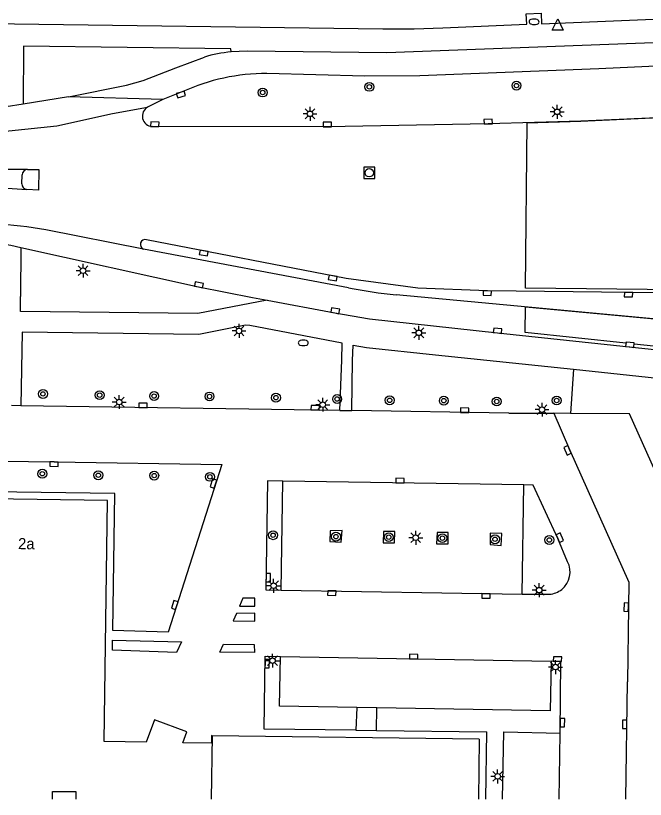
# Model space of a CAD drawing. Extents: x 132573 to 132944, y 398226 to 398676.
# Drawn here: x 132651.3 to 132708, y 398226.3 to 398296.9 of the extents above; entities that cross this region are included whole.
import ezdxf

# ---------------------------------------------------------------- set-up
doc = ezdxf.new("R2010")
doc.units = 0
for name, color, linetype in [('gg-anno-huisnummerreeks BGT', 7, 'Continuous'), ('gg-bbg-bijgebouw', 7, 'Continuous'), ('gg-bbg-hoofdgebouw', 7, 'Continuous'), ('gg-bbg-tussenscheiding', 7, 'Continuous'), ('gg-knt-verharding', 7, 'Continuous'), ('gg-knt-verharding nz', 7, 'Continuous'), ('gt-grn-groengrens', 7, 'Continuous'), ('gt-symb-boom', 7, 'Continuous'), ('gt-symb-brandkraan', 7, 'Continuous'), ('gt-symb-kolk', 7, 'Continuous'), ('gt-symb-lichtmast', 7, 'Continuous'), ('gt-symb-rioolschacht', 7, 'Continuous'), ('gt-symb-waterafsluiter', 7, 'Continuous'), ('ir-asfa-asfalt arcering', 7, 'Continuous'), ('ir-asfa-asfalt rood', 7, 'Continuous')]:
    doc.layers.add(name, color=color, linetype=linetype)

msp = doc.modelspace()

# ---------------------------------------------------------------- linework, layer by layer
at = {"layer": 'gg-bbg-bijgebouw'}
for q in [(132669.037, 398232.033), (132693.005, 398226.299)]:
    msp.add_line((132693.081, 398231.724), q, dxfattribs=at)
at = {"layer": 'gg-bbg-hoofdgebouw'}
msp.add_line((132654.642, 398226.299), (132654.65, 398227.008), dxfattribs=at)
for points in [[(132669.037, 398232.033), (132668.968, 398232.034), (132668.959, 398231.354), (132666.379, 398231.379), (132666.738, 398232.375), (132663.817, 398233.469), (132663.084, 398231.446), (132659.296, 398231.499), (132659.594, 398253.222), (132644.751, 398253.437)], [(132654.65, 398227.008), (132656.748, 398226.99), (132656.743, 398226.299)]]:
    msp.add_lwpolyline(points, dxfattribs=at)
at = {"layer": 'gg-bbg-tussenscheiding'}
msp.add_line((132669.037, 398232.033), (132668.946, 398226.299), dxfattribs=at)
at = {"layer": 'gg-knt-verharding'}
for p, q in [((132652.023, 398294.151), (132651.99, 398288.915)), ((132665.755, 398292.203), (132668.318, 398293.165)), ((132666.369, 398290.048), (132664.567, 398289.34)), ((132656.09, 398289.574), (132651.99, 398288.915)), ((132664.567, 398289.34), (132656.09, 398289.574)), ((132664.567, 398289.34), (132663.212, 398288.654)), ((132652.393, 398283.027), (132649.013, 398283.031)), ((132651.891, 398281.742), (132651.895, 398282.544)), ((132648.993, 398281.456), (132652.319, 398281.231)), ((132651.786, 398276.006), (132651.766, 398271.608)), ((132681.291, 398272.381), (132662.846, 398275.871)), ((132724.373, 398268.129), (132685.592, 398271.736)), ((132672.662, 398271.512), (132673.971, 398271.264)), ((132651.906, 398268.372), (132651.797, 398261.747)), ((132651.797, 398261.747), (132650.951, 398261.76)), ((132680.53, 398261.337), (132651.797, 398261.747)), ((132680.53, 398261.337), (132681.612, 398261.338)), ((132695.746, 398261.077), (132681.612, 398261.338)), ((132695.746, 398261.077), (132699.791, 398261.072)), ((132701.319, 398261.059), (132699.791, 398261.072)), ((132674.011, 398254.983), (132673.865, 398245.174)), ((132675.393, 398254.962), (132674.011, 398254.983)), ((132675.241, 398245.145), (132675.393, 398254.962)), ((132696.954, 398244.777), (132697.089, 398254.629)), ((132697.93, 398254.611), (132697.089, 398254.629)), ((132673.865, 398245.174), (132675.241, 398245.145)), ((132696.954, 398244.777), (132699.42, 398244.766)), ((132673.808, 398239.18), (132675.174, 398239.171)), ((132699.559, 398238.736), (132699.486, 398234.262)), ((132700.439, 398238.726), (132699.559, 398238.736)), ((132700.369, 398232.25), (132700.439, 398238.726)), ((132682.043, 398234.568), (132681.957, 398232.528)), ((132683.872, 398234.536), (132682.043, 398234.568)), ((132683.826, 398232.506), (132683.872, 398234.536)), ((132699.486, 398234.262), (132683.872, 398234.536)), ((132681.957, 398232.528), (132683.826, 398232.506)), ((132683.826, 398232.506), (132693.755, 398232.39)), ((132693.68, 398226.299), (132693.755, 398232.39))]:
    msp.add_line(p, q, dxfattribs=at)
for points in [[(132641.795, 398296.302), (132648.956, 398296.181), (132684.391, 398295.715), (132687.235, 398295.695), (132689.791, 398295.782), (132697.371, 398296.112), (132697.318, 398297.051), (132698.666, 398297.112), (132698.695, 398296.159), (132713.84, 398296.787), (132716.243, 398298.031), (132718.865, 398298.287), (132721.089, 398298.822)], [(132715.972, 398294.725), (132684.747, 398293.547), (132672.177, 398293.687), (132671.452, 398293.676), (132670.729, 398293.626)], [(132670.729, 398293.626), (132670.696, 398293.918), (132652.023, 398294.151)], [(132656.09, 398289.574), (132661.316, 398290.625), (132662.811, 398291.045), (132665.755, 398292.203)], [(132716.072, 398292.658), (132703.845, 398292.111), (132687.719, 398291.469), (132682.765, 398291.453), (132673.952, 398291.69)], [(132651.99, 398288.915), (132650.473, 398288.671), (132649.708, 398288.596)], [(132724.539, 398288.616), (132710.496, 398287.759), (132702.248, 398287.375), (132693.89, 398287.149), (132679.391, 398286.885), (132663.62, 398286.911)], [(132652.393, 398283.027), (132653.403, 398283.028), (132653.387, 398281.182), (132652.319, 398281.231)], [(132724.668, 398271.755), (132693.813, 398272.093), (132687.563, 398272.351), (132681.105, 398273.227), (132663.109, 398276.707)], [(132649.536, 398276.343), (132650.385, 398276.294), (132650.888, 398276.205), (132651.786, 398276.006)], [(132651.786, 398276.006), (132667.79, 398272.455), (132672.662, 398271.512)], [(132673.971, 398271.264), (132667.718, 398270.065), (132651.76, 398270.254), (132651.766, 398271.608)], [(132673.971, 398271.264), (132680.079, 398270.108), (132683.188, 398269.568), (132694.714, 398268.311), (132723.823, 398265.242)], [(132680.53, 398261.337), (132680.715, 398265.855), (132680.74, 398267.401), (132672.416, 398268.975), (132672.033, 398269.023), (132667.829, 398268.177), (132651.906, 398268.372)], [(132681.612, 398261.338), (132681.675, 398265.839), (132681.722, 398267.224), (132682.936, 398267.007), (132689.144, 398266.333), (132701.574, 398265.046)], [(132701.574, 398265.046), (132715.024, 398263.598), (132719.046, 398263.257)], [(132711.191, 398250.839), (132706.624, 398261.016), (132701.319, 398261.059)], [(132626.867, 398257.057), (132654.785, 398256.69), (132669.886, 398256.449)], [(132669.886, 398256.449), (132665.058, 398241.351), (132660.06, 398241.502), (132660.243, 398253.839), (132644.759, 398254.063)], [(132701.043, 398247.707), (132700.16, 398249.784), (132697.93, 398254.611)], [(132680.648, 398249.47), (132680.734, 398250.501), (132679.663, 398250.485), (132679.633, 398249.516), (132680.648, 398249.47)], [(132685.435, 398249.405), (132685.475, 398250.411), (132684.446, 398250.436), (132684.424, 398249.402), (132685.435, 398249.405)], [(132690.285, 398249.304), (132690.298, 398250.341), (132689.282, 398250.321), (132689.236, 398249.311), (132690.285, 398249.304)], [(132695.127, 398250.252), (132694.076, 398250.269), (132694.053, 398249.253), (132695.055, 398249.169), (132695.127, 398250.252)], [(132672.866, 398243.684), (132672.881, 398244.411), (132671.794, 398244.417), (132671.479, 398243.7), (132672.866, 398243.684)], [(132672.852, 398242.344), (132672.859, 398243.056), (132671.221, 398243.042), (132670.926, 398242.368), (132672.852, 398242.344)], [(132666.274, 398240.482), (132665.81, 398239.513), (132660.055, 398239.747), (132660.054, 398240.641), (132666.274, 398240.482)], [(132669.725, 398239.567), (132670.039, 398240.265), (132672.819, 398240.242), (132672.827, 398239.518), (132669.725, 398239.567)], [(132681.957, 398232.528), (132673.703, 398232.624), (132673.808, 398239.18)], [(132682.043, 398234.568), (132675.103, 398234.69), (132675.174, 398239.171)], [(132695.178, 398226.299), (132695.306, 398232.364), (132700.369, 398232.25)]]:
    msp.add_lwpolyline(points, dxfattribs=at)
for centre, radius, start, end in [((132672.022, 398280.326), 13.363, 95.5547, 106.09469), ((132673.958, 398273.331), 18.359, 90.01888, 114.41718), ((132663.664, 398287.84), 0.931, 119.03995, 267.30913), ((132652.395, 398282.527), 0.5, 90.25109, 177.99688), ((132652.378, 398281.715), 0.488, 176.82866, 263.06863), ((132662.991, 398276.285), 0.438, 74.34625, 250.72729), ((132690.707, 398320.509), 49.041, 258.92976, 264.01262), ((132699.232, 398246.788), 2.031, 308.96553, 26.90135), ((132699.231, 398246.791), 2.034, 275.3344, 308.93812)]:
    msp.add_arc(centre, radius, start, end, dxfattribs=at)
at = {"layer": 'gg-knt-verharding nz'}
for p, q in [((132662.846, 398275.871), (132654.053, 398277.599)), ((132697.089, 398254.629), (132675.393, 398254.962)), ((132675.241, 398245.145), (132696.954, 398244.777)), ((132675.174, 398239.171), (132699.559, 398238.736)), ((132706.292, 398226.299), (132706.437, 398236.895)), ((132700.287, 398226.299), (132700.369, 398232.25))]:
    msp.add_line(p, q, dxfattribs=at)
for points in [[(132595.104, 398287.061), (132636.866, 398286.381), (132649.245, 398286.381), (132655.041, 398286.969), (132660.032, 398288.081), (132663.212, 398288.654)], [(132699.791, 398261.072), (132701.213, 398257.819), (132706.561, 398245.852), (132706.518, 398243.601), (132706.437, 398236.895)]]:
    msp.add_lwpolyline(points, dxfattribs=at)
msp.add_arc((132647.794, 398243.162), 35.001, 79.69889, 87.3244, dxfattribs=at)
at = {"layer": 'gt-grn-groengrens'}
msp.add_line((132701.574, 398265.046), (132701.319, 398261.059), dxfattribs=at)
at = {"layer": 'gt-symb-boom'}
for centre, radius in [((132683.182, 398290.477), 0.4), ((132683.182, 398290.477), 0.2), ((132696.435, 398290.592), 0.4), ((132696.435, 398290.592), 0.2), ((132673.57, 398289.966), 0.4), ((132673.57, 398289.966), 0.2), ((132653.779, 398262.816), 0.4), ((132653.779, 398262.816), 0.2), ((132658.892, 398262.706), 0.4), ((132658.892, 398262.706), 0.2), ((132663.793, 398262.623), 0.4), ((132663.793, 398262.623), 0.2), ((132668.788, 398262.589), 0.4), ((132668.788, 398262.589), 0.2), ((132674.766, 398262.479), 0.4), ((132674.766, 398262.479), 0.2), ((132680.28, 398262.358), 0.4), ((132680.28, 398262.358), 0.2), ((132685.016, 398262.243), 0.4), ((132685.016, 398262.243), 0.2), ((132689.89, 398262.208), 0.4), ((132694.661, 398262.134), 0.4), ((132700.057, 398262.225), 0.4), ((132700.057, 398262.225), 0.2), ((132689.89, 398262.208), 0.2), ((132694.661, 398262.134), 0.2), ((132653.722, 398255.627), 0.4), ((132653.722, 398255.627), 0.2), ((132658.769, 398255.491), 0.4), ((132658.769, 398255.491), 0.2), ((132663.804, 398255.462), 0.4), ((132663.804, 398255.462), 0.2), ((132668.823, 398255.345), 0.4), ((132668.823, 398255.345), 0.2), ((132674.511, 398250.088), 0.4), ((132674.511, 398250.088), 0.2), ((132680.171, 398249.962), 0.4), ((132680.171, 398249.962), 0.2), ((132684.932, 398249.916), 0.4), ((132684.932, 398249.916), 0.2), ((132689.766, 398249.823), 0.4), ((132689.766, 398249.823), 0.2), ((132694.499, 398249.726), 0.4), ((132694.499, 398249.726), 0.2), ((132699.394, 398249.66), 0.4), ((132699.394, 398249.66), 0.2)]:
    msp.add_circle(centre, radius, dxfattribs=at)
at = {"layer": 'gt-symb-brandkraan'}
for centre, radius, start, end in [((132697.774, 398296.351), 0.206, 104.74122, 249.60736), ((132698.485, 398293.649), 3, 104.06633, 104.74122), ((132697.984, 398295.649), 0.938, 70.28224, 104.06633), ((132697.288, 398293.708), 3, 69.60734, 70.28224), ((132698.262, 398296.327), 0.206, 284.74121, 69.60734), ((132698.748, 398298.97), 3, 249.60736, 250.28226), ((132698.052, 398297.029), 0.938, 250.28226, 284.06631), ((132697.551, 398299.029), 3, 284.06631, 284.74121), ((132676.991, 398267.414), 0.206, 107.56694, 252.43307), ((132677.834, 398264.75), 3, 106.89205, 107.56694), ((132677.235, 398266.723), 0.938, 73.10799, 106.89205), ((132676.636, 398264.75), 3, 72.43309, 73.10799), ((132677.479, 398267.414), 0.206, 287.56695, 72.43309), ((132677.834, 398270.078), 3, 252.43307, 253.10797), ((132677.235, 398268.105), 0.938, 253.10797, 286.89206), ((132676.636, 398270.078), 3, 286.89206, 287.56695)]:
    msp.add_arc(centre, radius, start, end, dxfattribs=at)
at = {"layer": 'gt-symb-kolk'}
for points in [[(132666.151, 398289.979), (132665.794, 398289.865), (132665.915, 398289.484), (132666.63, 398289.712), (132666.508, 398290.093), (132666.151, 398289.979)], [(132663.854, 398286.908), (132664.229, 398286.903), (132664.235, 398287.303), (132663.485, 398287.313), (132663.479, 398286.913), (132663.854, 398286.908)], [(132679.391, 398286.885), (132679.766, 398286.885), (132679.766, 398287.285), (132679.016, 398287.285), (132679.016, 398286.885), (132679.391, 398286.885)], [(132693.89, 398287.149), (132694.265, 398287.156), (132694.258, 398287.556), (132693.508, 398287.542), (132693.515, 398287.142), (132693.89, 398287.149)], [(132668.301, 398275.707), (132667.933, 398275.778), (132667.857, 398275.385), (132668.594, 398275.243), (132668.669, 398275.636), (132668.301, 398275.707)], [(132679.927, 398273.457), (132679.559, 398273.528), (132679.483, 398273.136), (132680.219, 398272.993), (132680.295, 398273.386), (132679.927, 398273.457)], [(132667.79, 398272.455), (132668.158, 398272.384), (132668.234, 398272.776), (132667.498, 398272.919), (132667.422, 398272.526), (132667.79, 398272.455)], [(132693.813, 398272.093), (132693.438, 398272.108), (132693.422, 398271.709), (132694.171, 398271.678), (132694.188, 398272.078), (132693.813, 398272.093)], [(132706.531, 398271.954), (132706.156, 398271.958), (132706.152, 398271.558), (132706.902, 398271.55), (132706.906, 398271.95), (132706.531, 398271.954)], [(132680.079, 398270.108), (132680.448, 398270.044), (132680.517, 398270.438), (132679.778, 398270.566), (132679.71, 398270.172), (132680.079, 398270.108)], [(132694.714, 398268.311), (132695.087, 398268.271), (132695.129, 398268.669), (132694.383, 398268.748), (132694.341, 398268.351), (132694.714, 398268.311)], [(132706.637, 398267.046), (132707.01, 398267.007), (132707.052, 398267.405), (132706.306, 398267.483), (132706.264, 398267.085), (132706.637, 398267.046)], [(132662.79, 398261.58), (132663.165, 398261.574), (132663.171, 398261.974), (132662.421, 398261.986), (132662.415, 398261.586), (132662.79, 398261.58)], [(132678.298, 398261.372), (132678.673, 398261.367), (132678.678, 398261.767), (132677.928, 398261.777), (132677.923, 398261.377), (132678.298, 398261.372)], [(132691.777, 398261.149), (132692.152, 398261.143), (132692.159, 398261.543), (132691.409, 398261.555), (132691.402, 398261.155), (132691.777, 398261.149)], [(132701.213, 398257.819), (132701.063, 398258.163), (132700.696, 398258.002), (132700.997, 398257.315), (132701.363, 398257.475), (132701.213, 398257.819)], [(132654.785, 398256.69), (132654.41, 398256.695), (132654.404, 398256.295), (132655.154, 398256.285), (132655.16, 398256.685), (132654.785, 398256.69)], [(132669.331, 398254.698), (132669.444, 398255.055), (132669.063, 398255.176), (132668.836, 398254.461), (132669.218, 398254.341), (132669.331, 398254.698)], [(132685.931, 398254.814), (132686.306, 398254.808), (132686.313, 398255.208), (132685.563, 398255.22), (132685.556, 398254.82), (132685.931, 398254.814)], [(132700.16, 398249.784), (132700.317, 398249.444), (132700.68, 398249.611), (132700.366, 398250.292), (132700.003, 398250.124), (132700.16, 398249.784)], [(132673.877, 398246.272), (132673.871, 398245.897), (132674.271, 398245.891), (132674.283, 398246.641), (132673.883, 398246.647), (132673.877, 398246.272)], [(132679.807, 398245.076), (132679.432, 398245.082), (132679.426, 398244.682), (132680.176, 398244.67), (132680.182, 398245.07), (132679.807, 398245.076)], [(132693.696, 398244.823), (132693.321, 398244.83), (132693.314, 398244.43), (132694.064, 398244.416), (132694.071, 398244.816), (132693.696, 398244.823)], [(132665.843, 398243.744), (132665.957, 398244.101), (132665.575, 398244.223), (132665.348, 398243.508), (132665.729, 398243.387), (132665.843, 398243.744)], [(132706.518, 398243.601), (132706.525, 398243.976), (132706.125, 398243.984), (132706.111, 398243.234), (132706.511, 398243.226), (132706.518, 398243.601)], [(132687.182, 398238.958), (132687.557, 398238.951), (132687.564, 398239.351), (132686.814, 398239.365), (132686.807, 398238.965), (132687.182, 398238.958)], [(132700.126, 398238.73), (132700.501, 398238.721), (132700.511, 398239.121), (132699.761, 398239.139), (132699.751, 398238.739), (132700.126, 398238.73)], [(132673.786, 398238.521), (132673.774, 398238.146), (132674.173, 398238.133), (132674.198, 398238.883), (132673.798, 398238.896), (132673.786, 398238.521)], [(132700.379, 398233.209), (132700.374, 398232.834), (132700.774, 398232.829), (132700.784, 398233.579), (132700.384, 398233.584), (132700.379, 398233.209)], [(132706.381, 398233.043), (132706.386, 398233.418), (132705.986, 398233.424), (132705.976, 398232.674), (132706.376, 398232.668), (132706.381, 398233.043)]]:
    msp.add_lwpolyline(points, dxfattribs=at)
at = {"layer": 'gt-symb-lichtmast'}
for p, q in [((132677.838, 398288.295), (132677.838, 398288.67)), ((132699.927, 398288.407), (132699.662, 398288.672)), ((132700.104, 398288.48), (132700.104, 398288.855)), ((132700.281, 398288.407), (132700.546, 398288.672)), ((132677.588, 398288.045), (132677.213, 398288.045)), ((132677.661, 398288.222), (132677.396, 398288.487)), ((132677.661, 398287.868), (132677.396, 398287.603)), ((132678.015, 398288.222), (132678.28, 398288.487)), ((132678.28, 398287.603), (132678.015, 398287.868)), ((132678.088, 398288.045), (132678.463, 398288.045)), ((132699.854, 398288.23), (132699.479, 398288.23)), ((132699.927, 398288.053), (132699.662, 398287.788)), ((132700.104, 398287.98), (132700.104, 398287.605)), ((132700.546, 398287.788), (132700.281, 398288.053)), ((132700.354, 398288.23), (132700.729, 398288.23)), ((132677.838, 398287.795), (132677.838, 398287.42)), ((132657.393, 398274.166), (132657.393, 398274.541)), ((132657.143, 398273.916), (132656.768, 398273.916)), ((132657.216, 398274.093), (132656.951, 398274.358)), ((132657.216, 398273.739), (132656.951, 398273.474)), ((132657.57, 398274.093), (132657.835, 398274.358)), ((132657.835, 398273.474), (132657.57, 398273.739)), ((132657.643, 398273.916), (132658.018, 398273.916)), ((132657.393, 398273.666), (132657.393, 398273.291)), ((132671.267, 398268.67), (132671.002, 398268.935)), ((132671.444, 398268.743), (132671.444, 398269.118)), ((132671.621, 398268.67), (132671.886, 398268.935)), ((132687.642, 398268.569), (132687.642, 398268.944)), ((132671.194, 398268.493), (132670.819, 398268.493)), ((132671.267, 398268.316), (132671.002, 398268.051)), ((132671.444, 398268.243), (132671.444, 398267.868)), ((132671.886, 398268.051), (132671.621, 398268.316)), ((132671.694, 398268.493), (132672.069, 398268.493)), ((132687.392, 398268.319), (132687.017, 398268.319)), ((132687.465, 398268.496), (132687.2, 398268.761)), ((132687.465, 398268.142), (132687.2, 398267.877)), ((132687.642, 398268.069), (132687.642, 398267.694)), ((132687.819, 398268.496), (132688.084, 398268.761)), ((132688.084, 398267.877), (132687.819, 398268.142)), ((132687.892, 398268.319), (132688.267, 398268.319)), ((132660.473, 398262.263), (132660.208, 398262.528)), ((132660.65, 398262.336), (132660.65, 398262.711)), ((132660.827, 398262.263), (132661.092, 398262.528)), ((132678.986, 398262.095), (132678.986, 398262.47)), ((132660.4, 398262.086), (132660.025, 398262.086)), ((132660.473, 398261.909), (132660.208, 398261.644)), ((132660.65, 398261.836), (132660.65, 398261.461)), ((132661.092, 398261.644), (132660.827, 398261.909)), ((132660.9, 398262.086), (132661.275, 398262.086)), ((132678.736, 398261.845), (132678.361, 398261.845)), ((132678.809, 398262.022), (132678.544, 398262.287)), ((132679.163, 398262.022), (132679.428, 398262.287)), ((132679.236, 398261.845), (132679.611, 398261.845)), ((132698.565, 398261.578), (132698.3, 398261.843)), ((132698.742, 398261.651), (132698.742, 398262.026)), ((132698.919, 398261.578), (132699.184, 398261.843)), ((132678.809, 398261.668), (132678.544, 398261.403)), ((132678.986, 398261.595), (132678.986, 398261.22)), ((132679.428, 398261.403), (132679.163, 398261.668)), ((132698.492, 398261.401), (132698.117, 398261.401)), ((132698.565, 398261.224), (132698.3, 398260.959)), ((132698.742, 398261.151), (132698.742, 398260.776)), ((132699.184, 398260.959), (132698.919, 398261.224)), ((132698.992, 398261.401), (132699.367, 398261.401)), ((132687.362, 398250.112), (132687.362, 398250.487)), ((132687.112, 398249.862), (132686.737, 398249.862)), ((132687.185, 398250.039), (132686.92, 398250.304)), ((132687.539, 398250.039), (132687.804, 398250.304)), ((132687.612, 398249.862), (132687.987, 398249.862)), ((132687.185, 398249.685), (132686.92, 398249.42)), ((132687.362, 398249.612), (132687.362, 398249.237)), ((132687.804, 398249.42), (132687.539, 398249.685)), ((132674.305, 398245.539), (132673.93, 398245.539)), ((132674.378, 398245.716), (132674.113, 398245.981)), ((132674.555, 398245.789), (132674.555, 398246.164)), ((132674.732, 398245.716), (132674.997, 398245.981)), ((132674.805, 398245.539), (132675.18, 398245.539)), ((132698.305, 398245.315), (132698.04, 398245.58)), ((132698.482, 398245.388), (132698.482, 398245.763)), ((132698.659, 398245.315), (132698.924, 398245.58)), ((132674.378, 398245.362), (132674.113, 398245.097)), ((132674.555, 398245.289), (132674.555, 398244.914)), ((132674.997, 398245.097), (132674.732, 398245.362)), ((132698.232, 398245.138), (132697.857, 398245.138)), ((132698.305, 398244.961), (132698.04, 398244.696)), ((132698.482, 398244.888), (132698.482, 398244.513)), ((132698.924, 398244.696), (132698.659, 398244.961)), ((132698.732, 398245.138), (132699.107, 398245.138)), ((132674.28, 398238.966), (132674.015, 398239.231)), ((132674.457, 398239.039), (132674.457, 398239.414)), ((132674.634, 398238.966), (132674.899, 398239.231)), ((132674.207, 398238.789), (132673.832, 398238.789)), ((132674.28, 398238.612), (132674.015, 398238.347)), ((132674.457, 398238.539), (132674.457, 398238.164)), ((132674.899, 398238.347), (132674.634, 398238.612)), ((132674.707, 398238.789), (132675.082, 398238.789)), ((132699.781, 398238.39), (132699.516, 398238.655)), ((132699.958, 398238.463), (132699.958, 398238.838)), ((132700.135, 398238.39), (132700.4, 398238.655)), ((132699.708, 398238.213), (132699.333, 398238.213)), ((132699.781, 398238.036), (132699.516, 398237.771)), ((132699.958, 398237.963), (132699.958, 398237.588)), ((132700.4, 398237.771), (132700.135, 398238.036)), ((132700.208, 398238.213), (132700.583, 398238.213)), ((132694.563, 398228.54), (132694.298, 398228.805)), ((132694.74, 398228.613), (132694.74, 398228.988)), ((132694.917, 398228.54), (132695.182, 398228.805)), ((132694.49, 398228.363), (132694.115, 398228.363)), ((132694.563, 398228.186), (132694.298, 398227.921)), ((132694.74, 398228.113), (132694.74, 398227.738)), ((132695.182, 398227.921), (132694.917, 398228.186)), ((132694.99, 398228.363), (132695.365, 398228.363))]:
    msp.add_line(p, q, dxfattribs=at)
for centre in [(132677.838, 398288.045), (132700.104, 398288.23), (132657.393, 398273.916), (132671.444, 398268.493), (132687.642, 398268.319), (132660.65, 398262.086), (132678.986, 398261.845), (132698.742, 398261.401), (132687.362, 398249.862), (132674.555, 398245.539), (132698.482, 398245.138), (132674.457, 398238.789), (132699.958, 398238.213), (132694.74, 398228.363)]:
    msp.add_circle(centre, 0.25, dxfattribs=at)
at = {"layer": 'gt-symb-rioolschacht'}
msp.add_lwpolyline([(132682.674, 398282.234), (132683.674, 398282.234), (132683.674, 398283.234), (132682.674, 398283.234)], close=True, dxfattribs=at)
msp.add_circle((132683.174, 398282.734), 0.375, dxfattribs=at)
at = {"layer": 'gt-symb-waterafsluiter'}
for p, q in [((132699.657, 398295.594), (132700.157, 398296.594)), ((132700.157, 398296.594), (132700.657, 398295.594)), ((132700.657, 398295.594), (132699.657, 398295.594))]:
    msp.add_line(p, q, dxfattribs=at)
at = {"layer": 'ir-asfa-asfalt arcering'}
msp.add_lwpolyline([(132711.851, 398281.643), (132725.443, 398281.559), (132727.725, 398281.529), (132727.404, 398272.021), (132727.398, 398272.021), (132724.671, 398272.055), (132697.263, 398272.355), (132697.408, 398287.244), (132702.248, 398287.375), (132709.993, 398287.736), (132709.993, 398287.734), (132710.743, 398287.768), (132710.742, 398287.774), (132724.539, 398288.616), (132727.105, 398289.149), (132727.186, 398288.757), (132727.92, 398288.909), (132727.993, 398288.965), (132727.787, 398284.519), (132727.771, 398284.518), (132727.77, 398284.518), (132725.475, 398284.362), (132711.748, 398283.476), (132711.746, 398283.476)], dxfattribs=at)
at = {"layer": 'ir-asfa-asfalt rood'}
msp.add_lwpolyline([(132723.883, 398265.536), (132723.854, 398265.54), (132721.714, 398265.766), (132721.725, 398265.865), (132720.979, 398265.944), (132720.969, 398265.845), (132707.042, 398267.313), (132707.052, 398267.405), (132706.306, 398267.483), (132706.296, 398267.392), (132697.223, 398268.348), (132697.246, 398270.652), (132724.373, 398268.129), (132726.549, 398267.954)], dxfattribs=at)

# ---------------------------------------------------------------- texts
at = {"layer": 'gg-anno-huisnummerreeks BGT'}
msp.add_text('2a', height=1, rotation=359.2, dxfattribs=at).set_placement((132651.533, 398248.837))

doc.saveas('drawing.dxf')
